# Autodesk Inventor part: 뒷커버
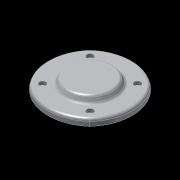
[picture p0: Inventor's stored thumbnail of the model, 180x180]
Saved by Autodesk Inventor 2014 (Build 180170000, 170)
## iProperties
Company: 한국ATC센터
Created: 2014-08
Part Number: 뒷커버
Document SubType Name: Modeling
Designer: KYOUNG IL JANG
Density: 2.71 g/cm^3
Material: 알루미늄 6061
Appearance: 알루미늄 - 평지
Mass: 260.104 g
Surface Area: 228.849 cm^2
Volume: 95.9792 cm^3
Author: KYOUNG IL JANG
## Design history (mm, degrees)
sketch "스케치1"
  geometry: C1 r 30 at (0, 0) reference; A1 r 53.623 centre (0, -3.623) between (36.062, 36.062) and (-36.062, 36.062) reference; A2 r 53.623 centre (3.623, 0) between (-36.062, 36.062) and (-36.062, -36.062) reference; A3 r 53.623 centre (-3.623, 0) between (36.062, -36.062) and (36.062, 36.062) reference; A4 r 53.623 centre (0, 3.623) between (-36.062, -36.062) and (36.062, -36.062) reference; 1 further point
  node "참조9"
  node "참조14"
  node "참조15"
  node "참조16"
  node "참조17"
extrude "돌출1" new body sketch "스케치1" distance "d0" = 8; taper "d1" = 0 deg
sketch "스케치2"
  geometry: C1 r 30 at (0, 0); 1 further point
  constraints: 1 centre point, 1 coincident
  dimensions: "d2" = 60 diameter of C1
extrude "돌출2" join sketch "스케치2" distance "d3" = 7; taper "d4" = -30 deg
sketch "스케치3"
  geometry: C1 r 1.621 at (28.284, 28.284) reference; C2 r 1.621 at (-28.284, 28.284) reference; C3 r 1.621 at (-28.284, -28.284) reference; C4 r 1.621 at (28.284, -28.284) reference; 1 further point
hole "구멍2" sketch "스케치3" at (-28.284, -28.284), (-28.284, 28.284), (28.284, 28.284), (28.284, -28.284) diameter "d14" = 4.5; stored, may be unused: countersink angle "d18" = 90 deg, drill point angle "d20" = 118 deg; dims "d15" = 6, "d16" = 8, "d17" = 4.4, "d19" = 20
extrude "돌출3" join sketch "스케치1" distance "d21" = 12; taper "d22" = 0 deg
hole "구멍3" diameter "d25" = 30; stored, may be unused: countersink angle "d29" = 90 deg, drill point angle "d31" = 0 deg; dims "d23" = 10, "d24" = 10, "d26" = 6, "d27" = 40, "d28" = 12, "d30" = 15
fillet "모깎기1" dims "d32" = 3, "d33" = 0.3
chamfer "모따기1" distance "d34" = 1; stored, may be unused: second distance "d35" = 2, angle "d36" = 45 deg
node "솔리드1"
node "참조18"
node "참조19"
node "참조20"
node "참조21"
